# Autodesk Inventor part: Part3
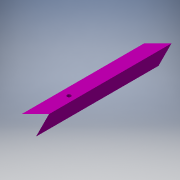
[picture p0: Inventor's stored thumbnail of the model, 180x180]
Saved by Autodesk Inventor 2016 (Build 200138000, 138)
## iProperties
Created: 2020-04
Part Number: Part3
Material: Generic
Document SubType Name: Modeling
Designer: merlin
Density: 1 g/cm^3
Appearance: Magenta
Author: merlin
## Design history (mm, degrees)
node "3D Sketch1"
sketch "Sketch1"
  geometry: L1 (376.238, -287.337)-(349.25, -287.337); L2 (349.25, -287.337)-(349.25, -584.2); L3 (349.25, -584.2)-(376.238, -584.2); L4 (376.238, -584.2)-(376.238, -287.337); 1 further point
  constraints: 8 end point, 2 parallel, 1 horizontal, 1 perpendicular
extrude "Extrusion1" new body sketch "Sketch1" distance "d0" = 25.4; taper "d1" = 0 deg
hole "Hole1" diameter "d4" = 7.62; stored, may be unused: countersink angle "d8" = 82 deg, drill point angle "d10" = 118 deg; dims "d2" = 25.4, "d3" = 25.4, "d5" = 19.05, "d6" = 9.525, "d7" = 6.35, "d9" = 25.4
body "Solid1"
